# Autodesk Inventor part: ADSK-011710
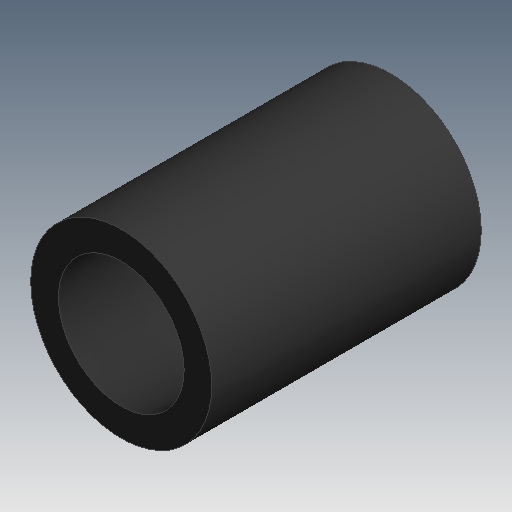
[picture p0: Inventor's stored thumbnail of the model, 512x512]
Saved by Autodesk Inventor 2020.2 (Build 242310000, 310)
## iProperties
Created: 2000-10
Part Number: ADSK-011710
Document SubType Name: Modeling
Designer: wymerj
Material: Générique
Density: 1 g/cm^3
Appearance: Rubber-Black
Mass: 113.01 g
Surface Area: 285.427 cm^2
Volume: 113.01 cm^3
Control State: 0
Master: False
Checked Out: False
Shininess: 0.0
Length Units: 11272
Angle Units: 11279
Time Units: 11290
Mass Units: 11286
Length Display Precision: 3
Angle Display Precision: 2
Compacted: True
Dimensions: 2,2x3,4x2,3 in
Mass: 0,249 lb
VLT_Material: Generic
Density: 0.0
Volumn: 0.0
Area: 0.0
PropertySet Name: Model Information
Author: wymerj
Revision Number: -
Title: ADSK-011710
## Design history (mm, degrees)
node "Extrusion1" dims "d2" = 85.09, "d3" = 0
node "Solide1"
node "Corps solides"
node "Corps surfaciques"
sketch "Sketch1"
  geometry: C1 r 19.844 at (155.953, 17.587); C2 r 28.575 at (155.953, 17.587)
  constraints: 2 centre point, 1 coincident
  dimensions: "d0" = 39.6875 diameter of C1; "d1" = 57.15 diameter of C2
